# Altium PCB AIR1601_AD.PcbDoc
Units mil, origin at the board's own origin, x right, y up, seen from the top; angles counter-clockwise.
Board outline 6000 x 4000 mil, 2 copper layers (Top, Bottom), stack 12.7 mil thick; 1 components, 0 nets, 86 pads, 0 vias.
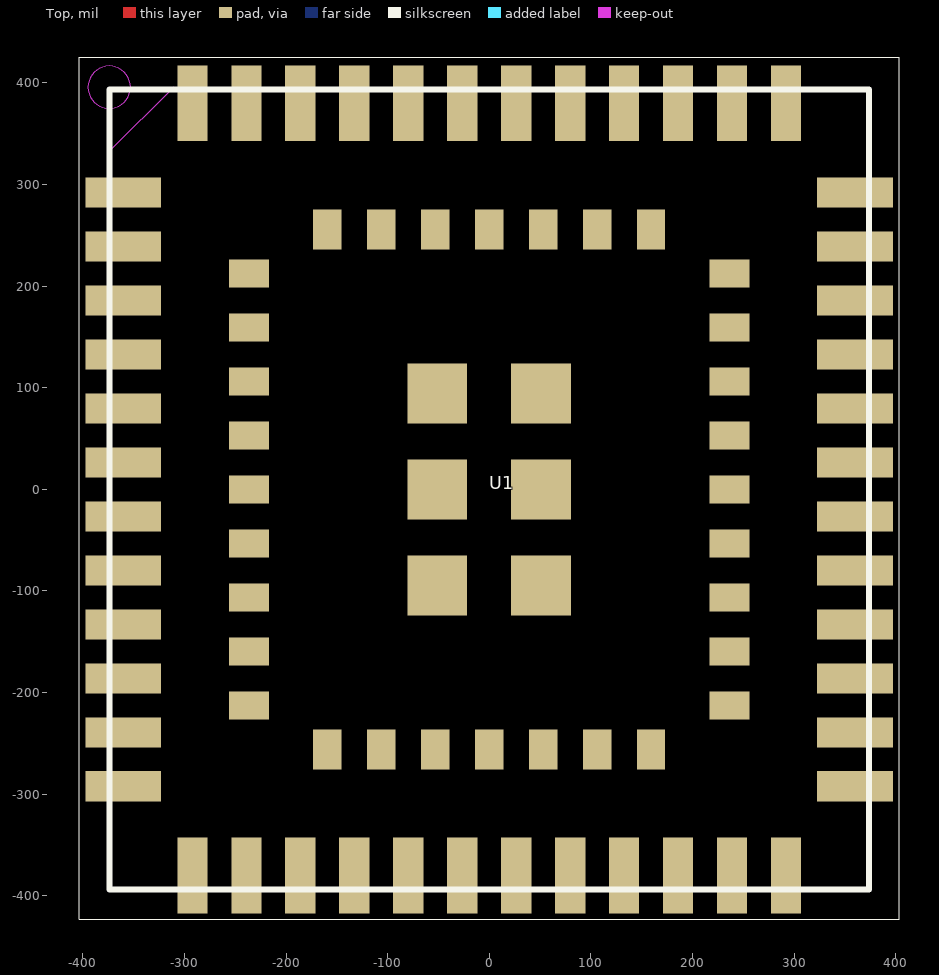
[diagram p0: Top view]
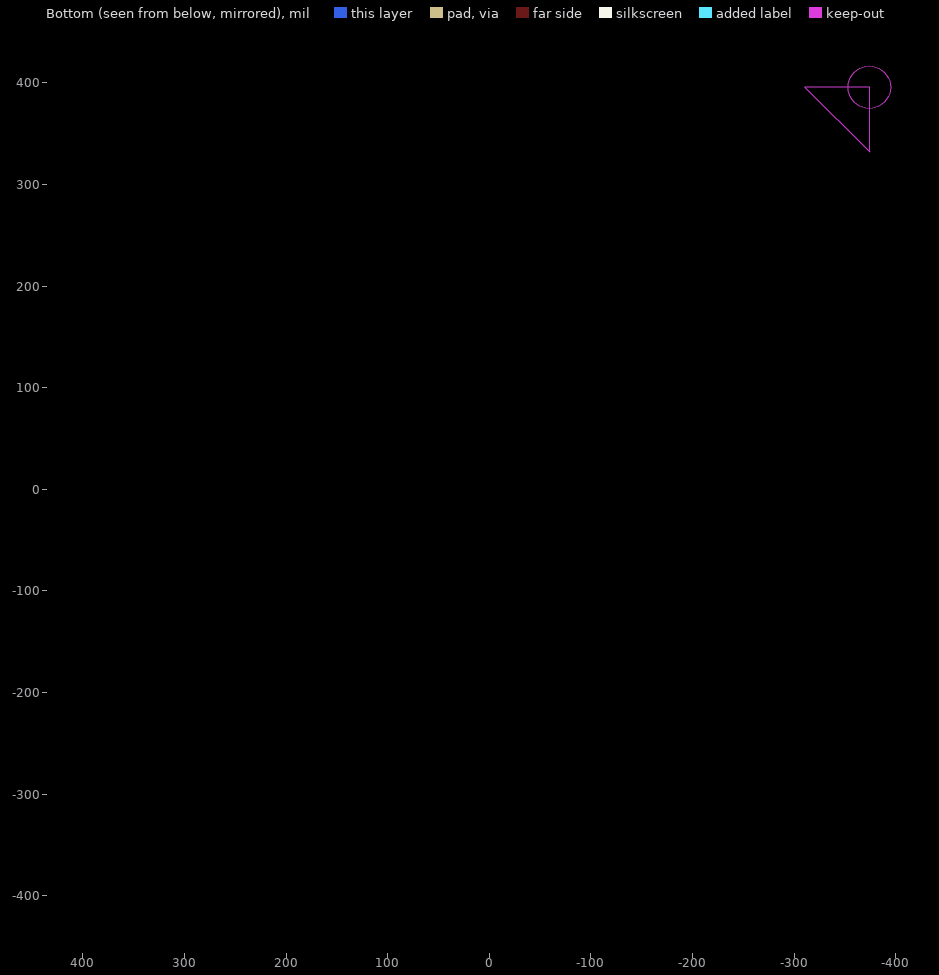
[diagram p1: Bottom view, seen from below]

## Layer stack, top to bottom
Top: signal copper 1.35
Dielectric: dielectric 10, FR-4, Dk 4.3
Bottom: signal copper 1.35

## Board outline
-9000,-9000 -3000,-9000 -3000,-5000 -9000,-5000

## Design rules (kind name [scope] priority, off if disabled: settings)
Clearance [All] p1: gap=10
PolygonConnect [All] p1: connectstyle=Relief reliefconductorwidth=10 reliefentries=4 polygonreliefangle="90 Angle" airgapwidth=10
RoutingVias [All] p1: holewidth=28 width=50 viastyle="Through Hole" minholewidth=28 minwidth=50 maxholewidth=28 maxwidth=50
SolderMaskExpansion [All] p1: expansion=4
Width [All] p1: maxlimit=10 minlimit=10 preferedwidth=10
28 further rules are at their usual default settings.

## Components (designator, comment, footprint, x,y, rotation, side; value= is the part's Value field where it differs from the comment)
U1 "AIR1601_19X20_PADS" AIR1601_19X20_PADS 0,0 r0 top

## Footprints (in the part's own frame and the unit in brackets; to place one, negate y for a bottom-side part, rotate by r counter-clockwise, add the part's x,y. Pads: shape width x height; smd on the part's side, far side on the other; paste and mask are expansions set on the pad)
AIR1601_19X20_PADS [mm]
  rect 1.9x0.75 smd: 1(-9.15,7.425) 2(-9.15,6.075) 3(-9.15,4.725) 4(-9.15,3.375) 5(-9.15,2.025) 6(-9.15,0.675) 7(-9.15,-0.675) 8(-9.15,-2.025) 9(-9.15,-3.375) 10(-9.15,-4.725) 11(-9.15,-6.075) 12(-9.15,-7.425) 25(9.15,-7.425) 26(9.15,-6.075) 27(9.15,-4.725) 28(9.15,-3.375) 29(9.15,-2.025) 30(9.15,-0.675) 31(9.15,0.675) 32(9.15,2.025) 33(9.15,3.375) 34(9.15,4.725) 35(9.15,6.075) 36(9.15,7.425)
  rect 0.75x1.9 smd: 13(-7.425,-9.65) 14(-6.075,-9.65) 15(-4.725,-9.65) 16(-3.375,-9.65) 17(-2.025,-9.65) 18(-0.675,-9.65) 19(0.675,-9.65) 20(2.025,-9.65) 21(3.375,-9.65) 22(4.725,-9.65) 23(6.075,-9.65) 24(7.425,-9.65) 37(7.425,9.65) 38(6.075,9.65) 39(4.725,9.65) 40(3.375,9.65) 41(2.025,9.65) 42(0.675,9.65) 43(-0.675,9.65) 44(-2.025,9.65) 45(-3.375,9.65) 46(-4.725,9.65) 47(-6.075,9.65) 48(-7.425,9.65)
  rect 1x0.7 smd: 49(-6,5.4) 50(-6,4.05) 51(-6,2.7) 52(-6,1.35) 53(-6,0) 54(-6,-1.35) 55(-6,-2.7) 56(-6,-4.05) 57(-6,-5.4) 65(6,-5.4) 66(6,-4.05) 67(6,-2.7) 68(6,-1.35) 69(6,0) 70(6,1.35) 71(6,2.7) 72(6,4.05) 73(6,5.4)
  rect 0.7x1 smd: 58(-4.05,-6.5) 59(-2.7,-6.5) 60(-1.35,-6.5) 61(0,-6.5) 62(1.35,-6.5) 63(2.7,-6.5) 64(4.05,-6.5) 74(4.05,6.5) 75(2.7,6.5) 76(1.35,6.5) 77(0,6.5) 78(-1.35,6.5) 79(-2.7,6.5) 80(-4.05,6.5)
  rect 1.5x1.5 smd: 81(-1.3,2.4) 82(-1.3,0) 83(-1.3,-2.4) 84(1.3,-2.4) 85(1.3,0) 86(1.3,2.4)
  Keep-Out Layer region: -9.507,10.051 -7.892,10.051 -9.507,8.436 -9.507,10.051
  Keep-Out Layer region: -8.968,10.05 -9.009,10.253 -9.124,10.426 -9.297,10.541 -9.5,10.582 -9.5,10.582 -9.703,10.541 -9.876,10.426 -9.991,10.253 -10.032,10.05 -10.032,10.05 -9.991,9.847 -9.876,9.674 -9.703,9.559 -9.5,9.518 -9.5,9.518 -9.297,9.559 -9.124,9.674 -9.009,9.847 -8.968,10.05
  silkscreen extent -10.25,-10.75 10.25,10.8

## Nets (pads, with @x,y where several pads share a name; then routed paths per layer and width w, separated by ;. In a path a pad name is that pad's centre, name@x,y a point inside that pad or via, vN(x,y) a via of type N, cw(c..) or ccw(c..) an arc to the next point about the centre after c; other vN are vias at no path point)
pads on no net: U1.1 U1.2 U1.3 U1.4 U1.5 U1.6 U1.7 U1.8 U1.9 U1.10 U1.11 U1.12 U1.13 U1.14 U1.15 U1.16 U1.17 U1.18 U1.19 U1.20 U1.21 U1.22 U1.23 U1.24 U1.25 U1.26 U1.27 U1.28 U1.29 U1.30 U1.31 U1.32 U1.33 U1.34 U1.35 U1.36 U1.37 U1.38 U1.39 U1.40 U1.41 U1.42 U1.43 U1.44 U1.45 U1.46 U1.47 U1.48 U1.49 U1.50 U1.51 U1.52 U1.53 U1.54 U1.55 U1.56 U1.57 U1.58 U1.59 U1.60 U1.61 U1.62 U1.63 U1.64 U1.65 U1.66 U1.67 U1.68 U1.69 U1.70 U1.71 U1.72 U1.73 U1.74 U1.75 U1.76 U1.77 U1.78 U1.79 U1.80 U1.81 U1.82 U1.83 U1.84 U1.85 U1.86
